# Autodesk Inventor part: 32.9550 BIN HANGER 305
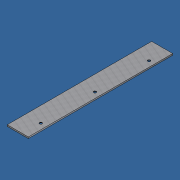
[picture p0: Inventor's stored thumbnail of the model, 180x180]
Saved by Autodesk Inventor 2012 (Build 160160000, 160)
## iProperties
Created: 2013-07
Part Number: 32.9550 BIN HANGER 305
Material: Aluminum-6061
Description: BIN HANGER 305
Document SubType Name: Modeling
Designer: Admin
Stock Number: 20.9229 AL BARSTOCK 1/8" x 1.75"
Density: 2.71 g/cm^3
Author: Admin
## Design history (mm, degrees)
sketch "Sketch1"
  geometry: L1 (-22.225, -1.588)-(22.225, -1.587); L2 (22.225, -1.587)-(22.225, 1.587); L3 (22.225, 1.587)-(-22.225, 1.587); L4 (-22.225, 1.587)-(-22.225, -1.588); 3 further points
  constraints: 8 end point, 2 midpoint, 2 parallel, 1 horizontal, 1 horizontal alignment, 1 perpendicular, 1 vertical alignment
  dimensions: "d0" = 44.45 distance of L2.end L3.end; "d1" = 3.175 distance of L3.end L1.start
extrude "Extrusion2" new body sketch "Sketch1" stored distance "d4" = 305; taper "d5" = 0 deg
sketch "Sketch2"
  geometry: L1 (44.45, 0)-(0, 0) reference; L2 (0, -305)-(44.45, -305) reference; L3 (44.45, -305)-(44.45, 0) reference; 4 further points
  constraints: 2 vertical alignment
  dimensions: "d6" = 38.1 distance from line of point (32.664, -38.1) L1; "d7" = 38.1 distance from line of point (32.664, -266.9) L2; "d8" = 11.7856 distance from line of point (32.664, -38.1) L3; "d9" = 228.8 distance of point (32.664, -266.9) point (32.664, -38.1) (derived); "d10" = 114.4 distance of point (32.664, -152.5) point (32.664, -38.1) (= 0.5 x d9)
hole "Hole1" sketch "Sketch2" at (32.664, -38.1), (32.664, -152.5), (32.664, -266.9) diameter "d11" = 5.5; stored, may be unused: countersink angle "d15" = 90 deg, drill point angle "d17" = 118 deg; dims "d12" = 19.05, "d13" = 11, "d14" = 6.35, "d16" = 25.4
body "Solid1"
